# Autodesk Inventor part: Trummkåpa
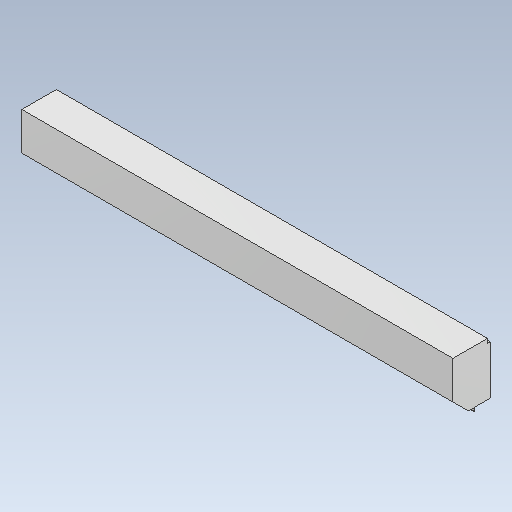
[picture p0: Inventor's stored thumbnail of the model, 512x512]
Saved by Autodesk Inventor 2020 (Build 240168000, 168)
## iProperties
Created: 2019-06
Part Number: Trummkåpa
Material: Aluminum
Document SubType Name: Modeling
Designer: cl
Density: 2.7 g/cm^3
Appearance: Satin
Author: cl
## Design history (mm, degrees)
sketch "Sketch1"
  geometry: L1 (0, 0)-(20, 0); L2 (20, 0)-(20, 32.56); L3 (20, 32.56)-(107.427, 119.987); L4 (107.427, 119.987)-(320.917, 119.987); L5 (320.917, 119.987)-(320.917, -75.013); L6 (320.917, -75.013)-(296.917, -75.013); L7 (296.917, -75.013)-(296.917, -90.013); L8 (296.917, -90.013)-(20.987, -90.013); L9 (0, 0)-(0, -2); L10 (0, -2)-(20.987, -2); L11 (20.987, -2)-(20.987, -90.013)
  constraints: 22 end point, 7 perpendicular, 1 horizontal, 1 parallel, 1 vertical
  dimensions: "d0" = 20 distance of L1.start L1.end; "d1" = 32.56 distance of L1.end L2.end; "d2" = 123.64 distance of L2.end L3.end; "d3" = 135 deg angle of L2 L3; "d4" = 213.49 distance of L3.end L4.end; "d5" = 195 distance of L4.end L5.end; "d6" = 24 distance of L5.end L6.end; "d7" = 15 distance of L6.end L7.end; "d8" = 275.93 distance of L7.end L8.end; "d10" = 2 distance of L1.start L9.end
extrude "Extrusion1" new body sketch "Sketch1" distance "d11" = 2432 (computed from Dagbredd); taper "d12" = 0 deg
body "Solid1"
other parameters: "Daghöjd" = 3254, "Dagbredd" = 2222
